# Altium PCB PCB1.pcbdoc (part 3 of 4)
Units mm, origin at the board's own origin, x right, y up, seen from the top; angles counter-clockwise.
Board outline 96.27 x 122.17 mm, 4 copper layers (Top Layer, Inner1, Inner2, Bottom Layer); 129 components, 127 nets, 708 pads, 342 vias.
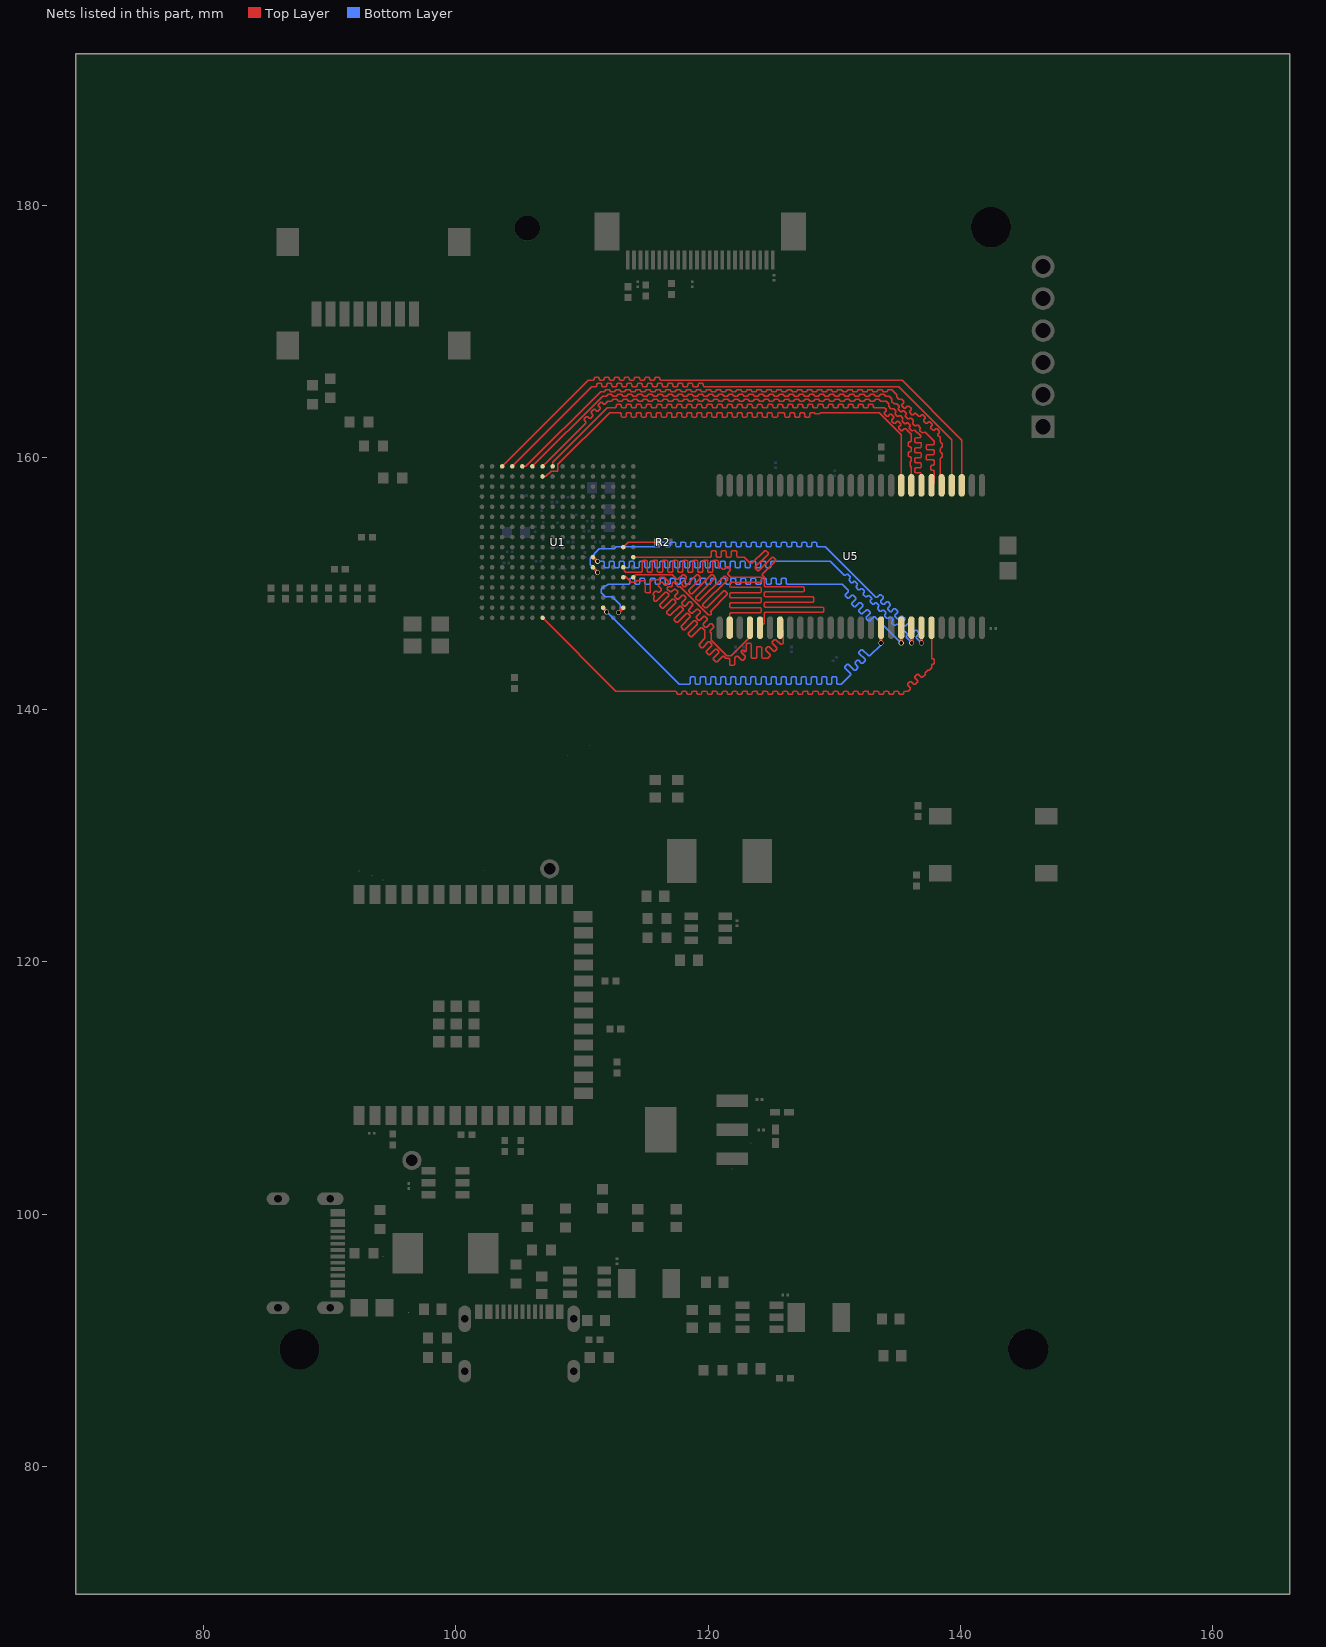
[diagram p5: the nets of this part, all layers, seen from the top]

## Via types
v1: diameter 0.4, hole 0.3, Top Layer to Bottom Layer, 308 vias
v2: diameter 1, hole 0.5, Top Layer to Bottom Layer, 33 vias
v3: diameter 0.5, hole 0.3, Top Layer to Bottom Layer, 1 vias

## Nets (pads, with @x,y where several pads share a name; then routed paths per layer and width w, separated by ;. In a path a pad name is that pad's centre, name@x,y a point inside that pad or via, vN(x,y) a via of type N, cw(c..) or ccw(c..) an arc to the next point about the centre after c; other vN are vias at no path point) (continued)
SD_A5: U1.A3 U5.30 | length 46.8
  Top Layer w0.1: U1.A3@103.677,159.289 110.504,166.116 110.896,166.116 110.967,166.187 110.967,166.27 111.038,166.341 111.296,166.341 111.367,166.27 111.367,166.187 111.438,166.116 111.696,166.116 111.767,166.187 111.767,166.27 111.838,166.341 112.096,166.341 112.167,166.27 112.167,166.187 112.238,166.116 112.496,166.116 112.567,166.187 112.567,166.27 112.638,166.341 112.896,166.341 112.967,166.27 112.967,166.187 113.038,166.116 113.296,166.116 113.367,166.187 113.367,166.27 113.438,166.341 113.696,166.341 113.767,166.27 113.767,166.187 113.838,166.116 114.096,166.116 114.167,166.187 114.167,166.27 114.238,166.341 114.496,166.341 114.567,166.27 114.567,166.187 114.638,166.116 114.896,166.116 114.967,166.187 114.967,166.27 115.038,166.341 115.296,166.341 115.367,166.27 115.367,166.187 115.438,166.116 115.696,166.116 115.767,166.187 115.767,166.27 115.838,166.341 116.096,166.341 116.167,166.27 116.167,166.187 116.238,166.116 135.382,166.116 140.118,161.38 U5.30@140.118,157.788
SD_A6: U1.A4 U5.31 | length 46.7
  Top Layer w0.1: U1.A4@104.477,159.289 110.796,165.608 111.096,165.608 111.167,165.679 111.167,165.791 111.237,165.862 111.496,165.862 111.567,165.791 111.567,165.679 111.637,165.608 111.896,165.608 111.967,165.679 111.967,165.791 112.037,165.862 112.296,165.862 112.367,165.791 112.367,165.679 112.437,165.608 112.696,165.608 112.767,165.679 112.767,165.791 112.837,165.862 113.096,165.862 113.167,165.791 113.167,165.679 113.237,165.608 113.496,165.608 113.567,165.679 113.567,165.791 113.637,165.862 113.896,165.862 113.967,165.791 113.967,165.679 114.037,165.608 114.296,165.608 114.367,165.679 114.367,165.791 114.437,165.862 114.696,165.862 114.767,165.791 114.767,165.679 114.837,165.608 115.096,165.608 115.167,165.679 115.167,165.791 115.237,165.862 115.496,165.862 115.567,165.791 115.567,165.679 115.637,165.608 115.896,165.608 115.967,165.679 115.967,165.791 116.037,165.862 116.296,165.862 116.367,165.791 116.367,165.679 116.437,165.608 116.732,165.608 116.803,165.679 116.803,165.809 116.874,165.879 117.132,165.879 117.203,165.809 117.203,165.679 117.274,165.608 117.532,165.608 117.603,165.679 117.603,165.809 117.674,165.879 117.932,165.879 118.003,165.809 118.003,165.679 118.074,165.608 118.332,165.608 118.403,165.679 118.403,165.809 118.474,165.879 118.732,165.879 118.803,165.809 118.803,165.679 118.874,165.608 119.132,165.608 119.203,165.679 119.203,165.809 119.274,165.879 119.532,165.879 119.603,165.809 119.603,165.679 119.674,165.608 135.128,165.608 139.318,161.418 U5.31@139.318,157.788
SD_A7: U1.A5 U5.32 | length 46.8
  Top Layer w0.1: U1.A5@105.277,159.289 105.537,159.289 111.475,165.227 111.775,165.227 111.902,165.354 112.175,165.354 112.302,165.227 112.575,165.227 112.702,165.354 112.975,165.354 113.102,165.227 113.375,165.227 113.502,165.354 113.775,165.354 113.902,165.227 114.175,165.227 114.302,165.354 114.575,165.354 114.702,165.227 114.975,165.227 115.102,165.354 115.375,165.354 115.502,165.227 115.775,165.227 115.902,165.354 116.175,165.354 116.302,165.227 116.575,165.227 116.702,165.354 116.975,165.354 117.102,165.227 117.375,165.227 117.502,165.354 117.775,165.354 117.902,165.227 118.175,165.227 118.302,165.354 118.575,165.354 118.702,165.227 118.975,165.227 119.102,165.354 119.375,165.354 119.502,165.227 119.775,165.227 119.902,165.354 120.175,165.354 120.302,165.227 120.575,165.227 120.702,165.354 120.975,165.354 121.102,165.227 121.375,165.227 121.502,165.354 121.775,165.354 121.902,165.227 122.175,165.227 122.302,165.354 122.575,165.354 122.702,165.227 122.975,165.227 123.102,165.354 123.375,165.354 123.502,165.227 123.775,165.227 123.902,165.354 124.175,165.354 124.302,165.227 124.575,165.227 124.702,165.354 124.975,165.354 125.102,165.227 125.375,165.227 125.502,165.354 125.775,165.354 125.902,165.227 126.175,165.227 126.302,165.354 126.575,165.354 126.702,165.227 126.975,165.227 127.102,165.354 127.375,165.354 127.502,165.227 127.775,165.227 127.902,165.354 128.175,165.354 128.302,165.227 128.575,165.227 128.702,165.354 128.975,165.354 129.102,165.227 129.375,165.227 129.502,165.354 129.775,165.354 129.902,165.227 130.175,165.227 130.302,165.354 130.575,165.354 130.702,165.227 130.975,165.227 131.102,165.354 131.375,165.354 131.502,165.227 131.775,165.227 131.902,165.354 132.175,165.354 132.302,165.227 132.575,165.227 132.702,165.354 132.975,165.354 133.102,165.227 133.375,165.227 133.502,165.354 133.775,165.354 133.902,165.227 134.175,165.227 134.302,165.354 134.575,165.354 134.947,164.982 134.947,164.803 135.13,164.62 135.23,164.62 135.242,164.632 135.342,164.632 135.525,164.449 135.525,164.349 135.371,164.195 135.371,164.095 135.553,163.912 135.653,163.912 135.808,164.066 135.908,164.066 136.091,163.883 136.091,163.783 135.985,163.678 135.985,163.578 136.168,163.395 136.268,163.395 136.373,163.501 136.473,163.501 136.707,163.267 136.807,163.267 136.926,163.386 137.026,163.386 137.208,163.203 137.208,163.103 137.09,162.984 137.09,162.884 137.272,162.702 137.372,162.702 137.491,162.82 137.591,162.82 137.774,162.638 137.774,162.538 137.655,162.419 137.655,162.319 137.838,162.136 137.938,162.136 138.057,162.255 138.157,162.255 138.34,162.072 138.34,161.972 138.221,161.853 138.221,161.753 138.391,161.583 138.391,161.243 138.462,161.172 138.486,161.172 138.557,161.101 138.557,160.843 138.486,160.772 138.462,160.772 138.391,160.701 138.391,160.443 138.462,160.372 138.486,160.372 138.557,160.301 138.557,160.043 138.486,159.972 138.462,159.972 138.391,159.901 138.391,157.915 U5.32@138.518,157.788
SD_A8: U1.A6 U5.33 | length 46.8
  Top Layer w0.1: U1.A6@106.077,159.289 111.634,164.846 111.934,164.846 112.005,164.917 112.005,164.927 112.075,164.998 112.334,164.998 112.405,164.927 112.405,164.917 112.475,164.846 112.734,164.846 112.805,164.917 112.805,164.927 112.875,164.998 113.134,164.998 113.205,164.927 113.205,164.917 113.275,164.846 113.534,164.846 113.605,164.917 113.605,164.927 113.675,164.998 113.934,164.998 114.005,164.927 114.005,164.917 114.075,164.846 114.334,164.846 114.405,164.917 114.405,164.927 114.475,164.998 114.734,164.998 114.805,164.927 114.805,164.917 114.875,164.846 115.134,164.846 115.205,164.917 115.205,164.927 115.275,164.998 115.534,164.998 115.605,164.927 115.605,164.917 115.675,164.846 115.934,164.846 116.005,164.917 116.005,164.927 116.075,164.998 116.334,164.998 116.405,164.927 116.405,164.917 116.475,164.846 116.734,164.846 116.805,164.917 116.805,164.927 116.875,164.998 117.134,164.998 117.205,164.927 117.205,164.917 117.275,164.846 117.534,164.846 117.605,164.917 117.605,164.927 117.675,164.998 117.934,164.998 118.005,164.927 118.005,164.917 118.075,164.846 118.334,164.846 118.405,164.917 118.405,164.927 118.475,164.998 118.734,164.998 118.805,164.927 118.805,164.917 118.875,164.846 119.134,164.846 119.205,164.917 119.205,164.927 119.275,164.998 119.534,164.998 119.605,164.927 119.605,164.917 119.675,164.846 119.934,164.846 120.005,164.917 120.005,164.927 120.075,164.998 120.334,164.998 120.405,164.927 120.405,164.917 120.475,164.846 120.734,164.846 120.805,164.917 120.805,164.927 120.875,164.998 121.134,164.998 121.205,164.927 121.205,164.917 121.275,164.846 121.534,164.846 121.605,164.917 121.605,164.927 121.675,164.998 121.934,164.998 122.005,164.927 122.005,164.917 122.075,164.846 122.334,164.846 122.405,164.917 122.405,164.927 122.475,164.998 122.734,164.998 122.805,164.927 122.805,164.917 122.875,164.846 123.134,164.846 123.205,164.917 123.205,164.927 123.275,164.998 123.534,164.998 123.605,164.927 123.605,164.917 123.675,164.846 123.934,164.846 124.005,164.917 124.005,164.927 124.075,164.998 124.334,164.998 124.405,164.927 124.405,164.917 124.475,164.846 124.734,164.846 124.805,164.917 124.805,164.927 124.875,164.998 125.134,164.998 125.205,164.927 125.205,164.917 125.275,164.846 125.534,164.846 125.605,164.917 125.605,164.927 125.675,164.998 125.934,164.998 126.005,164.927 126.005,164.917 126.075,164.846 126.334,164.846 126.405,164.917 126.405,164.927 126.475,164.998 126.734,164.998 126.805,164.927 126.805,164.917 126.875,164.846 127.134,164.846 127.205,164.917 127.205,164.927 127.275,164.998 127.534,164.998 127.605,164.927 127.605,164.917 127.675,164.846 127.934,164.846 128.005,164.917 128.005,164.927 128.075,164.998 128.334,164.998 128.405,164.927 128.405,164.917 128.475,164.846 128.734,164.846 128.805,164.917 128.805,164.927 128.875,164.998 129.134,164.998 129.205,164.927 129.205,164.917 129.275,164.846 129.534,164.846 129.605,164.917 129.605,164.927 129.675,164.998 129.934,164.998 130.005,164.927 130.005,164.917 130.075,164.846 130.334,164.846 130.405,164.917 130.405,164.927 130.475,164.998 130.734,164.998 130.805,164.927 130.805,164.917 130.875,164.846 131.134,164.846 131.205,164.917 131.205,164.927 131.275,164.998 131.534,164.998 131.605,164.927 131.605,164.917 131.675,164.846 131.934,164.846 132.005,164.917 132.005,164.927 132.075,164.998 132.334,164.998 132.405,164.927 132.405,164.917 132.475,164.846 132.734,164.846 132.805,164.917 132.805,164.927 132.875,164.998 133.134,164.998 133.205,164.927 133.205,164.917 133.275,164.846 133.534,164.846 133.605,164.917 133.605,164.927 133.675,164.998 133.934,164.998 134.005,164.927 134.005,164.917 134.075,164.846 134.366,164.846 134.578,164.634 134.578,164.534 134.566,164.522 134.566,164.422 134.749,164.239 134.849,164.239 134.861,164.251 134.961,164.251 135.144,164.068 135.144,163.968 135.088,163.913 135.088,163.813 135.271,163.63 135.371,163.63 135.427,163.685 135.527,163.685 135.71,163.502 135.71,163.402 135.654,163.347 135.654,163.247 135.837,163.064 135.937,163.064 135.992,163.12 136.092,163.12 136.275,162.937 136.275,162.837 136.22,162.781 136.22,162.681 136.403,162.499 136.503,162.499 136.558,162.554 136.658,162.554 136.841,162.371 136.841,162.271 136.794,162.225 136.794,162.125 136.977,161.942 137.077,161.942 137.124,161.988 137.224,161.988 137.922,161.29 137.922,161.069 137.851,160.998 137.358,160.998 137.287,160.927 137.287,160.669 137.358,160.598 137.851,160.598 137.922,160.527 137.922,160.269 137.851,160.198 137.358,160.198 137.287,160.127 137.287,159.869 137.358,159.798 137.851,159.798 137.922,159.727 137.922,159.444 137.851,159.373 137.739,159.373 137.668,159.302 137.668,159.044 137.739,158.973 137.851,158.973 137.922,158.902 137.922,157.992 U5.33@137.718,157.788
SD_A9: U1.A7 U5.34 | length 46.8
  Top Layer w0.1: U1.A7@106.877,159.289 110.308,162.72 110.308,162.82 110.17,162.958 110.17,163.058 110.353,163.24 110.453,163.24 110.591,163.103 110.691,163.103 110.874,163.285 110.874,163.385 110.736,163.523 110.736,163.623 110.918,163.806 111.018,163.806 111.156,163.668 111.256,163.668 111.439,163.851 111.439,163.951 111.301,164.089 111.301,164.189 111.484,164.372 111.584,164.372 111.722,164.234 111.822,164.234 112.053,164.465 112.353,164.465 112.424,164.536 112.424,164.546 112.495,164.617 112.753,164.617 112.824,164.546 112.824,164.536 112.895,164.465 113.153,164.465 113.224,164.536 113.224,164.546 113.295,164.617 113.553,164.617 113.624,164.546 113.624,164.536 113.695,164.465 113.953,164.465 114.024,164.536 114.024,164.546 114.095,164.617 114.353,164.617 114.424,164.546 114.424,164.536 114.495,164.465 114.753,164.465 114.824,164.536 114.824,164.546 114.895,164.617 115.153,164.617 115.224,164.546 115.224,164.536 115.295,164.465 115.553,164.465 115.624,164.536 115.624,164.546 115.695,164.617 115.953,164.617 116.024,164.546 116.024,164.536 116.095,164.465 116.353,164.465 116.424,164.536 116.424,164.546 116.495,164.617 116.753,164.617 116.824,164.546 116.824,164.536 116.895,164.465 117.153,164.465 117.224,164.536 117.224,164.546 117.295,164.617 117.553,164.617 117.624,164.546 117.624,164.536 117.695,164.465 117.953,164.465 118.024,164.536 118.024,164.546 118.095,164.617 118.353,164.617 118.424,164.546 118.424,164.536 118.495,164.465 118.753,164.465 118.824,164.536 118.824,164.546 118.895,164.617 119.153,164.617 119.224,164.546 119.224,164.536 119.295,164.465 119.553,164.465 119.624,164.536 119.624,164.546 119.695,164.617 119.953,164.617 120.024,164.546 120.024,164.536 120.095,164.465 120.353,164.465 120.424,164.536 120.424,164.546 120.495,164.617 120.753,164.617 120.824,164.546 120.824,164.536 120.895,164.465 121.153,164.465 121.224,164.536 121.224,164.546 121.295,164.617 121.553,164.617 121.624,164.546 121.624,164.536 121.695,164.465 121.953,164.465 122.024,164.536 122.024,164.546 122.095,164.617 122.353,164.617 122.424,164.546 122.424,164.536 122.495,164.465 122.753,164.465 122.824,164.536 122.824,164.546 122.895,164.617 123.153,164.617 123.224,164.546 123.224,164.536 123.295,164.465 123.553,164.465 123.624,164.536 123.624,164.546 123.695,164.617 123.953,164.617 124.024,164.546 124.024,164.536 124.095,164.465 124.353,164.465 124.424,164.536 124.424,164.546 124.495,164.617 124.753,164.617 124.824,164.546 124.824,164.536 124.895,164.465 125.153,164.465 125.224,164.536 125.224,164.546 125.295,164.617 125.553,164.617 125.624,164.546 125.624,164.536 125.695,164.465 125.953,164.465 126.024,164.536 126.024,164.546 126.095,164.617 126.353,164.617 126.424,164.546 126.424,164.536 126.495,164.465 126.753,164.465 126.824,164.536 126.824,164.546 126.895,164.617 127.153,164.617 127.224,164.546 127.224,164.536 127.295,164.465 127.553,164.465 127.624,164.536 127.624,164.546 127.695,164.617 127.953,164.617 128.024,164.546 128.024,164.536 128.095,164.465 128.353,164.465 128.424,164.536 128.424,164.546 128.495,164.617 128.753,164.617 128.824,164.546 128.824,164.536 128.895,164.465 129.153,164.465 129.224,164.536 129.224,164.546 129.295,164.617 129.553,164.617 129.624,164.546 129.624,164.536 129.695,164.465 129.953,164.465 130.024,164.536 130.024,164.546 130.095,164.617 130.353,164.617 130.424,164.546 130.424,164.536 130.495,164.465 130.753,164.465 130.824,164.536 130.824,164.546 130.895,164.617 131.153,164.617 131.224,164.546 131.224,164.536 131.295,164.465 131.553,164.465 131.624,164.536 131.624,164.546 131.695,164.617 131.953,164.617 132.024,164.546 132.024,164.536 132.095,164.465 132.353,164.465 132.424,164.536 132.424,164.546 132.495,164.617 132.753,164.617 132.824,164.546 132.824,164.536 132.895,164.465 133.153,164.465 133.224,164.536 133.224,164.546 133.295,164.617 133.553,164.617 133.624,164.546 133.624,164.536 133.695,164.465 134.112,164.465 134.324,164.253 134.324,164.153 134.312,164.141 134.312,164.041 134.495,163.858 134.595,163.858 134.607,163.87 134.707,163.87 134.89,163.687 134.89,163.587 134.834,163.532 134.834,163.432 135.017,163.249 135.117,163.249 135.173,163.304 135.273,163.304 135.456,163.121 135.456,163.021 135.4,162.966 135.4,162.866 135.583,162.683 135.683,162.683 135.738,162.739 135.838,162.739 136.021,162.556 136.021,162.456 135.966,162.4 135.966,162.3 136.149,162.118 136.249,162.118 136.304,162.173 136.404,162.173 136.847,161.73 136.847,161.651 136.777,161.58 136.469,161.58 136.398,161.51 136.398,161.251 136.469,161.18 136.847,161.18 136.918,161.11 136.918,160.851 136.847,160.78 136.469,160.78 136.398,160.71 136.398,160.451 136.469,160.38 136.847,160.38 136.918,160.31 136.918,160.051 136.847,159.98 136.469,159.98 136.398,159.91 136.398,159.651 136.469,159.58 136.847,159.58 136.918,159.51 136.918,159.251 136.847,159.18 136.469,159.18 136.398,159.11 136.398,158.851 136.469,158.78 136.847,158.78 136.918,158.71 U5.34@136.918,157.788
SD_A10: U1.T7 U5.22 | length 46.9
  Top Layer w0.1: U1.T7@106.877,147.289 112.688,141.478 117.449,141.478 117.519,141.407 117.519,141.295 117.59,141.224 117.849,141.224 117.919,141.295 117.919,141.407 117.99,141.478 118.249,141.478 118.319,141.407 118.319,141.295 118.39,141.224 118.649,141.224 118.719,141.295 118.719,141.407 118.79,141.478 119.049,141.478 119.119,141.407 119.119,141.295 119.19,141.224 119.449,141.224 119.519,141.295 119.519,141.407 119.59,141.478 119.849,141.478 119.919,141.407 119.919,141.295 119.99,141.224 120.249,141.224 120.319,141.295 120.319,141.407 120.39,141.478 120.649,141.478 120.719,141.407 120.719,141.295 120.79,141.224 121.049,141.224 121.119,141.295 121.119,141.407 121.19,141.478 121.449,141.478 121.519,141.407 121.519,141.295 121.59,141.224 121.849,141.224 121.919,141.295 121.919,141.407 121.99,141.478 122.249,141.478 122.319,141.407 122.319,141.295 122.39,141.224 122.649,141.224 122.719,141.295 122.719,141.407 122.79,141.478 123.049,141.478 123.119,141.407 123.119,141.295 123.19,141.224 123.449,141.224 123.519,141.295 123.519,141.407 123.59,141.478 123.849,141.478 123.919,141.407 123.919,141.295 123.99,141.224 124.249,141.224 124.319,141.295 124.319,141.407 124.39,141.478 124.649,141.478 124.719,141.407 124.719,141.295 124.79,141.224 125.049,141.224 125.119,141.295 125.119,141.407 125.19,141.478 125.449,141.478 125.519,141.407 125.519,141.295 125.59,141.224 125.849,141.224 125.919,141.295 125.919,141.407 125.99,141.478 126.249,141.478 126.319,141.407 126.319,141.295 126.39,141.224 126.649,141.224 126.719,141.295 126.719,141.407 126.79,141.478 127.049,141.478 127.119,141.407 127.119,141.295 127.19,141.224 127.449,141.224 127.519,141.295 127.519,141.407 127.59,141.478 127.849,141.478 127.919,141.407 127.919,141.295 127.99,141.224 128.249,141.224 128.319,141.295 128.319,141.407 128.39,141.478 128.649,141.478 128.719,141.407 128.719,141.295 128.79,141.224 129.049,141.224 129.119,141.295 129.119,141.407 129.19,141.478 129.449,141.478 129.519,141.407 129.519,141.295 129.59,141.224 129.849,141.224 129.919,141.295 129.919,141.407 129.99,141.478 130.249,141.478 130.319,141.407 130.319,141.295 130.39,141.224 130.649,141.224 130.719,141.295 130.719,141.407 130.79,141.478 131.049,141.478 131.119,141.407 131.119,141.295 131.19,141.224 131.449,141.224 131.519,141.295 131.519,141.407 131.59,141.478 131.849,141.478 131.919,141.407 131.919,141.295 131.99,141.224 132.249,141.224 132.319,141.295 132.319,141.407 132.39,141.478 132.649,141.478 132.719,141.407 132.719,141.295 132.79,141.224 133.049,141.224 133.119,141.295 133.119,141.407 133.19,141.478 133.449,141.478 133.519,141.407 133.519,141.295 133.59,141.224 133.849,141.224 133.919,141.295 133.919,141.407 133.99,141.478 134.249,141.478 134.319,141.407 134.319,141.295 134.39,141.224 134.649,141.224 134.719,141.295 134.719,141.407 134.79,141.478 135.049,141.478 135.119,141.407 135.119,141.295 135.19,141.224 135.449,141.224 135.519,141.295 135.519,141.407 135.59,141.478 135.89,141.478 136.044,141.632 136.044,141.732 135.826,141.949 135.826,142.049 136.009,142.232 136.109,142.232 136.327,142.015 136.427,142.015 136.61,142.198 136.61,142.298 136.392,142.515 136.392,142.615 136.575,142.798 136.675,142.798 136.893,142.581 136.993,142.581 137.202,142.79 137.202,142.931 137.414,143.143 137.555,143.143 137.718,143.306 137.718,143.549 137.789,143.62 137.851,143.62 137.922,143.69 137.922,143.949 137.851,144.02 137.789,144.02 137.718,144.09 U5.22@137.718,146.504
SD_A11: U1.A8 U5.35 | length 46.7
  Top Layer w0.1: U1.A8@107.677,159.289 107.677,159.62 112.014,163.957 112.645,163.957 112.716,164.028 112.716,164.14 112.786,164.211 113.045,164.211 113.116,164.14 113.116,164.028 113.186,163.957 113.445,163.957 113.516,164.028 113.516,164.14 113.586,164.211 113.845,164.211 113.916,164.14 113.916,164.028 113.986,163.957 114.245,163.957 114.316,164.028 114.316,164.14 114.386,164.211 114.645,164.211 114.716,164.14 114.716,164.028 114.786,163.957 115.045,163.957 115.116,164.028 115.116,164.14 115.186,164.211 115.445,164.211 115.516,164.14 115.516,164.028 115.586,163.957 115.845,163.957 115.916,164.028 115.916,164.14 115.986,164.211 116.245,164.211 116.316,164.14 116.316,164.028 116.386,163.957 116.645,163.957 116.716,164.028 116.716,164.14 116.786,164.211 117.045,164.211 117.116,164.14 117.116,164.028 117.186,163.957 117.445,163.957 117.516,164.028 117.516,164.14 117.586,164.211 117.845,164.211 117.916,164.14 117.916,164.028 117.986,163.957 118.245,163.957 118.316,164.028 118.316,164.14 118.386,164.211 118.645,164.211 118.716,164.14 118.716,164.028 118.786,163.957 119.045,163.957 119.116,164.028 119.116,164.14 119.186,164.211 119.445,164.211 119.516,164.14 119.516,164.028 119.586,163.957 119.845,163.957 119.916,164.028 119.916,164.14 119.986,164.211 120.245,164.211 120.316,164.14 120.316,164.028 120.386,163.957 120.645,163.957 120.716,164.028 120.716,164.14 120.786,164.211 121.045,164.211 121.116,164.14 121.116,164.028 121.186,163.957 121.445,163.957 121.516,164.028 121.516,164.14 121.586,164.211 121.845,164.211 121.916,164.14 121.916,164.028 121.986,163.957 122.245,163.957 122.316,164.028 122.316,164.14 122.386,164.211 122.645,164.211 122.716,164.14 122.716,164.028 122.786,163.957 123.045,163.957 123.116,164.028 123.116,164.14 123.186,164.211 123.445,164.211 123.516,164.14 123.516,164.028 123.586,163.957 123.845,163.957 123.916,164.028 123.916,164.14 123.986,164.211 124.245,164.211 124.316,164.14 124.316,164.028 124.386,163.957 124.645,163.957 124.716,164.028 124.716,164.14 124.786,164.211 125.045,164.211 125.116,164.14 125.116,164.028 125.186,163.957 125.445,163.957 125.516,164.028 125.516,164.14 125.586,164.211 125.845,164.211 125.916,164.14 125.916,164.028 125.986,163.957 126.245,163.957 126.316,164.028 126.316,164.14 126.386,164.211 126.645,164.211 126.716,164.14 126.716,164.028 126.786,163.957 127.045,163.957 127.116,164.028 127.116,164.14 127.186,164.211 127.445,164.211 127.516,164.14 127.516,164.028 127.586,163.957 127.845,163.957 127.916,164.028 127.916,164.14 127.986,164.211 128.245,164.211 128.316,164.14 128.316,164.028 128.386,163.957 128.645,163.957 128.716,164.028 128.716,164.14 128.786,164.211 129.045,164.211 129.116,164.14 129.116,164.028 129.186,163.957 129.445,163.957 129.516,164.028 129.516,164.14 129.586,164.211 129.845,164.211 129.916,164.14 129.916,164.028 129.986,163.957 130.245,163.957 130.316,164.028 130.316,164.14 130.386,164.211 130.645,164.211 130.716,164.14 130.716,164.028 130.786,163.957 131.045,163.957 131.116,164.028 131.116,164.14 131.186,164.211 131.445,164.211 131.516,164.14 131.516,164.028 131.586,163.957 131.845,163.957 131.916,164.028 131.916,164.14 131.986,164.211 132.245,164.211 132.316,164.14 132.316,164.028 132.386,163.957 132.645,163.957 132.716,164.028 132.716,164.14 132.786,164.211 133.045,164.211 133.116,164.14 133.116,164.028 133.186,163.957 133.985,163.957 134.14,163.802 134.14,163.702 133.986,163.548 133.986,163.448 134.169,163.265 134.269,163.265 134.423,163.419 134.523,163.419 134.706,163.236 134.706,163.136 134.552,162.982 134.552,162.882 134.735,162.699 134.835,162.699 134.989,162.853 135.089,162.853 135.272,162.67 135.272,162.57 135.118,162.416 135.118,162.316 135.301,162.133 135.401,162.133 135.555,162.287 135.655,162.287 136.118,161.824 136.118,161.306 136.047,161.235 135.961,161.235 135.89,161.164 135.89,160.906 135.961,160.835 136.047,160.835 136.118,160.764 136.118,160.506 136.047,160.435 135.961,160.435 135.89,160.364 135.89,160.106 135.961,160.035 136.047,160.035 136.118,159.964 136.118,159.742 136.017,159.641 136.017,159.342 136.118,159.241 U5.35@136.118,157.788
SD_A12: U1.B7 U5.36 | length 46.8
  Top Layer w0.1: U1.B7@106.877,158.489 107.137,158.489 107.555,158.907 108.07,158.907 108.095,158.932 108.095,159.447 112.197,163.549 113.037,163.549 113.108,163.478 113.108,163.239 113.178,163.168 113.437,163.168 113.508,163.239 113.508,163.478 113.578,163.549 113.837,163.549 113.908,163.478 113.908,163.239 113.978,163.168 114.237,163.168 114.308,163.239 114.308,163.478 114.378,163.549 114.637,163.549 114.708,163.478 114.708,163.239 114.778,163.168 115.037,163.168 115.108,163.239 115.108,163.478 115.178,163.549 115.437,163.549 115.508,163.478 115.508,163.239 115.578,163.168 115.837,163.168 115.908,163.239 115.908,163.478 115.978,163.549 116.237,163.549 116.308,163.478 116.308,163.239 116.378,163.168 116.637,163.168 116.708,163.239 116.708,163.478 116.778,163.549 117.037,163.549 117.108,163.478 117.108,163.239 117.178,163.168 117.437,163.168 117.508,163.239 117.508,163.478 117.578,163.549 117.837,163.549 117.908,163.478 117.908,163.239 117.978,163.168 118.237,163.168 118.308,163.239 118.308,163.478 118.378,163.549 118.637,163.549 118.708,163.478 118.708,163.239 118.778,163.168 119.037,163.168 119.108,163.239 119.108,163.478 119.178,163.549 119.437,163.549 119.508,163.478 119.508,163.239 119.578,163.168 119.837,163.168 119.908,163.239 119.908,163.478 119.978,163.549 120.237,163.549 120.308,163.478 120.308,163.239 120.378,163.168 120.637,163.168 120.708,163.239 120.708,163.478 120.778,163.549 121.037,163.549 121.108,163.478 121.108,163.239 121.178,163.168 121.437,163.168 121.508,163.239 121.508,163.478 121.578,163.549 121.837,163.549 121.908,163.478 121.908,163.239 121.978,163.168 122.237,163.168 122.308,163.239 122.308,163.478 122.378,163.549 122.637,163.549 122.708,163.478 122.708,163.239 122.778,163.168 123.037,163.168 123.108,163.239 123.108,163.478 123.178,163.549 123.437,163.549 123.508,163.478 123.508,163.239 123.578,163.168 123.837,163.168 123.908,163.239 123.908,163.478 123.978,163.549 124.237,163.549 124.308,163.478 124.308,163.239 124.378,163.168 124.637,163.168 124.708,163.239 124.708,163.478 124.778,163.549 125.037,163.549 125.108,163.478 125.108,163.239 125.178,163.168 125.437,163.168 125.508,163.239 125.508,163.478 125.578,163.549 125.993,163.549 126.063,163.478 126.063,163.266 126.134,163.195 126.393,163.195 126.463,163.266 126.463,163.478 126.534,163.549 126.793,163.549 126.863,163.478 126.863,163.266 126.934,163.195 127.193,163.195 127.263,163.266 127.263,163.478 127.334,163.549 127.593,163.549 127.663,163.478 127.663,163.266 127.734,163.195 127.993,163.195 128.063,163.266 128.063,163.478 128.134,163.549 128.416,163.549 128.516,163.449 128.816,163.449 128.916,163.549 133.577,163.549 135.318,161.808 U5.36@135.318,157.788
SD_BA0: U1.K12 U5.20 | length 46.8
  Top Layer w0.254: U1.K12@110.877,152.089 111.203,151.763 v1(111.25,151.763) ; U5.20@136.118,146.504 136.144,146.478 v1(136.144,145.288)
  Bottom Layer w0.1: v1(111.25,151.763) 111.691,151.763 111.762,151.693 111.762,151.337 111.833,151.266 112.091,151.266 112.162,151.337 112.162,151.693 112.233,151.763 112.491,151.763 112.562,151.693 112.562,151.337 112.633,151.266 112.891,151.266 112.962,151.337 112.962,151.693 113.033,151.763 113.291,151.763 113.362,151.693 113.362,151.337 113.433,151.266 113.691,151.266 113.762,151.337 113.762,151.693 113.833,151.763 114.091,151.763 114.162,151.693 114.162,151.337 114.233,151.266 114.491,151.266 114.562,151.337 114.562,151.693 114.633,151.763 114.891,151.763 114.962,151.693 114.962,151.337 115.033,151.266 115.291,151.266 115.362,151.337 115.362,151.693 115.433,151.763 115.691,151.763 115.762,151.693 115.762,151.337 115.833,151.266 116.091,151.266 116.162,151.337 116.162,151.693 116.233,151.763 116.491,151.763 116.562,151.693 116.562,151.337 116.633,151.266 116.891,151.266 116.962,151.337 116.962,151.693 117.033,151.763 117.291,151.763 117.362,151.693 117.362,151.337 117.433,151.266 117.691,151.266 117.762,151.337 117.762,151.693 117.833,151.763 118.091,151.763 118.162,151.693 118.162,151.337 118.233,151.266 118.491,151.266 118.562,151.337 118.562,151.693 118.633,151.763 118.891,151.763 118.962,151.693 118.962,151.337 119.033,151.266 119.291,151.266 119.362,151.337 119.362,151.693 119.433,151.763 119.691,151.763 119.762,151.693 119.762,151.337 119.833,151.266 120.091,151.266 120.162,151.337 120.162,151.693 120.233,151.763 120.491,151.763 120.562,151.693 120.562,151.337 120.633,151.266 120.891,151.266 120.962,151.337 120.962,151.693 121.033,151.763 121.291,151.763 121.362,151.693 121.362,151.337 121.433,151.266 121.691,151.266 121.762,151.337 121.762,151.693 121.833,151.763 122.091,151.763 122.162,151.693 122.162,151.337 122.233,151.266 122.491,151.266 122.562,151.337 122.562,151.693 122.633,151.763 122.891,151.763 122.962,151.693 122.962,151.337 123.033,151.266 123.291,151.266 123.362,151.337 123.362,151.693 123.433,151.763 123.691,151.763 123.762,151.693 123.762,151.337 123.833,151.266 124.091,151.266 124.162,151.337 124.162,151.693 124.233,151.763 124.491,151.763 124.562,151.693 124.562,151.337 124.633,151.266 124.891,151.266 124.962,151.337 124.962,151.693 125.033,151.763 129.669,151.763 130.793,150.639 130.893,150.639 130.983,150.73 131.083,150.73 131.266,150.547 131.266,150.447 131.176,150.356 131.176,150.256 131.358,150.074 131.458,150.074 131.549,150.164 131.649,150.164 131.832,149.981 131.832,149.881 131.741,149.791 131.741,149.691 131.924,149.508 132.024,149.508 132.115,149.598 132.215,149.598 132.397,149.416 132.397,149.316 132.307,149.225 132.307,149.125 132.49,148.942 132.59,148.942 132.68,149.033 132.78,149.033 132.963,148.85 132.963,148.75 132.873,148.659 132.873,148.559 133.055,148.377 133.155,148.377 133.246,148.467 133.346,148.467 133.529,148.284 133.529,148.184 133.438,148.094 133.438,147.994 133.621,147.811 133.721,147.811 133.812,147.901 133.912,147.901 134.095,147.718 134.095,147.618 134.004,147.528 134.004,147.428 134.187,147.245 134.287,147.245 134.377,147.336 134.477,147.336 134.66,147.153 134.66,147.053 134.57,146.962 134.57,146.862 134.753,146.679 134.853,146.679 134.943,146.77 135.043,146.77 135.226,146.587 135.226,146.487 135.135,146.397 135.135,146.297 135.318,146.114 135.418,146.114 135.509,146.204 135.609,146.204 135.792,146.021 135.792,145.921 135.701,145.831 135.701,145.731 v1(136.144,145.288)
SD_BA1: U1.L12 U5.21 | length 46.8
  Top Layer w0.254: U1.L12@110.877,151.289 111.252,150.914 v1(111.252,150.876) ; v1(136.918,145.288) U5.21@136.918,146.504
  Bottom Layer w0.1: v1(111.252,150.876) 110.648,151.48 110.648,152.013 111.389,152.753 112.581,152.753 112.736,152.908 116.151,152.908 116.222,152.979 116.222,153.218 116.293,153.289 116.551,153.289 116.622,153.218 116.622,152.979 116.693,152.908 116.951,152.908 117.022,152.979 117.022,153.218 117.093,153.289 117.351,153.289 117.422,153.218 117.422,152.979 117.493,152.908 117.751,152.908 117.822,152.979 117.822,153.218 117.893,153.289 118.151,153.289 118.222,153.218 118.222,152.979 118.293,152.908 118.551,152.908 118.622,152.979 118.622,153.218 118.693,153.289 118.951,153.289 119.022,153.218 119.022,152.979 119.093,152.908 119.351,152.908 119.422,152.979 119.422,153.218 119.493,153.289 119.751,153.289 119.822,153.218 119.822,152.979 119.893,152.908 120.151,152.908 120.222,152.979 120.222,153.218 120.293,153.289 120.551,153.289 120.622,153.218 120.622,152.979 120.693,152.908 120.951,152.908 121.022,152.979 121.022,153.218 121.093,153.289 121.351,153.289 121.422,153.218 121.422,152.979 121.493,152.908 121.751,152.908 121.822,152.979 121.822,153.218 121.893,153.289 122.151,153.289 122.222,153.218 122.222,152.979 122.293,152.908 122.551,152.908 122.622,152.979 122.622,153.218 122.693,153.289 122.951,153.289 123.022,153.218 123.022,152.979 123.093,152.908 123.351,152.908 123.422,152.979 123.422,153.218 123.493,153.289 123.751,153.289 123.822,153.218 123.822,152.979 123.893,152.908 124.151,152.908 124.222,152.979 124.222,153.218 124.293,153.289 124.551,153.289 124.622,153.218 124.622,152.979 124.693,152.908 124.951,152.908 125.022,152.979 125.022,153.218 125.093,153.289 125.351,153.289 125.422,153.218 125.422,152.979 125.493,152.908 125.751,152.908 125.822,152.979 125.822,153.218 125.893,153.289 126.151,153.289 126.222,153.218 126.222,152.979 126.293,152.908 126.551,152.908 126.622,152.979 126.622,153.218 126.693,153.289 126.951,153.289 127.022,153.218 127.022,152.979 127.093,152.908 127.351,152.908 127.422,152.979 127.422,153.218 127.493,153.289 127.751,153.289 127.822,153.218 127.822,152.979 127.893,152.908 128.151,152.908 128.222,152.979 128.222,153.218 128.293,153.289 128.551,153.289 128.622,153.218 128.622,152.979 128.693,152.908 129.298,152.908 133.297,148.908 133.397,148.908 133.609,149.12 133.709,149.12 133.892,148.937 133.892,148.837 133.68,148.626 133.68,148.526 133.863,148.343 133.963,148.343 134.175,148.554 134.275,148.554 134.458,148.371 134.458,148.271 134.246,148.06 134.246,147.96 134.429,147.777 134.529,147.777 134.74,147.989 134.84,147.989 135.023,147.806 135.023,147.706 134.812,147.494 134.812,147.394 134.995,147.211 135.095,147.211 135.306,147.423 135.406,147.423 135.589,147.24 135.589,147.14 135.377,146.929 135.377,146.829 135.56,146.646 135.66,146.646 135.872,146.857 135.972,146.857 136.155,146.674 136.155,146.574 135.943,146.363 135.943,146.263 136.126,146.08 136.226,146.08 136.437,146.292 136.537,146.292 136.72,146.109 136.72,146.009 136.509,145.797 136.509,145.697 v1(136.918,145.288)
SD_CAS_N: U1.R13 U5.17 | length 46.8
  Top Layer w0.254: U1.R13@111.677,148.089 111.677,148.041 v1(111.966,147.753) ; v1(133.718,145.288) U5.17@133.718,146.504
  Bottom Layer w0.1: v1(111.966,147.753) 117.709,142.009 118.529,142.009 118.6,142.08 118.6,142.55 118.67,142.621 118.929,142.621 119,142.55 119,142.08 119.07,142.009 119.329,142.009 119.4,142.08 119.4,142.55 119.47,142.621 119.729,142.621 119.8,142.55 119.8,142.08 119.87,142.009 120.129,142.009 120.2,142.08 120.2,142.55 120.27,142.621 120.529,142.621 120.6,142.55 120.6,142.08 120.67,142.009 120.929,142.009 121,142.08 121,142.55 121.07,142.621 121.329,142.621 121.4,142.55 121.4,142.08 121.47,142.009 121.729,142.009 121.8,142.08 121.8,142.55 121.87,142.621 122.129,142.621 122.2,142.55 122.2,142.08 122.27,142.009 122.529,142.009 122.6,142.08 122.6,142.55 122.67,142.621 122.929,142.621 123,142.55 123,142.08 123.07,142.009 123.329,142.009 123.4,142.08 123.4,142.55 123.47,142.621 123.729,142.621 123.8,142.55 123.8,142.08 123.87,142.009 124.129,142.009 124.2,142.08 124.2,142.55 124.27,142.621 124.529,142.621 124.6,142.55 124.6,142.08 124.67,142.009 124.929,142.009 125,142.08 125,142.55 125.07,142.621 125.329,142.621 125.4,142.55 125.4,142.08 125.47,142.009 125.729,142.009 125.8,142.08 125.8,142.55 125.87,142.621 126.129,142.621 126.2,142.55 126.2,142.08 126.27,142.009 126.529,142.009 126.6,142.08 126.6,142.55 126.67,142.621 126.929,142.621 127,142.55 127,142.08 127.07,142.009 127.329,142.009 127.4,142.08 127.4,142.55 127.47,142.621 127.729,142.621 127.8,142.55 127.8,142.08 127.87,142.009 128.129,142.009 128.2,142.08 128.2,142.55 128.27,142.621 128.529,142.621 128.6,142.55 128.6,142.08 128.67,142.009 128.929,142.009 129,142.08 129,142.55 129.07,142.621 129.329,142.621 129.4,142.55 129.4,142.08 129.47,142.009 129.729,142.009 129.8,142.08 129.8,142.55 129.87,142.621 130.129,142.621 130.2,142.55 130.2,142.08 130.27,142.009 130.57,142.009 131.313,142.751 131.313,142.851 130.845,143.319 130.845,143.419 131.028,143.602 131.128,143.602 131.596,143.134 131.696,143.134 131.878,143.317 131.878,143.417 131.653,143.643 131.653,143.743 131.836,143.926 131.936,143.926 132.161,143.7 132.261,143.7 132.444,143.883 132.444,143.983 131.96,144.467 131.96,144.567 132.143,144.749 132.243,144.749 132.727,144.266 132.827,144.266 133.718,145.157 v1(133.718,145.288)
SD_CLK: R2.2 U1.J15 | length 2.9
  Top Layer w0.1: U1.J15@113.277,152.889 113.677,153.289 R2.2@116.026,153.289
SD_CS_N: U1.R15 U5.19 | length 46.8
  Top Layer w0.254: v1(112.903,147.701) 113.277,148.075 U1.R15@113.277,148.089 ; v1(135.318,145.288) U5.19@135.318,146.504
  Bottom Layer w0.1: v1(112.903,147.701) 113.03,147.701 113.03,148.336 112.416,148.95 111.847,148.95 111.535,149.262 111.535,149.55 111.816,149.831 111.943,149.831 112.07,149.958 113.73,149.958 113.8,150.029 113.8,150.358 113.871,150.429 114.13,150.429 114.2,150.358 114.2,150.029 114.271,149.958 114.53,149.958 114.6,150.029 114.6,150.358 114.671,150.429 114.93,150.429 115,150.358 115,150.029 115.071,149.958 115.33,149.958 115.4,150.029 115.4,150.358 115.471,150.429 115.73,150.429 115.8,150.358 115.8,150.029 115.871,149.958 116.13,149.958 116.2,150.029 116.2,150.358 116.271,150.429 116.53,150.429 116.6,150.358 116.6,150.029 116.671,149.958 116.93,149.958 117,150.029 117,150.358 117.071,150.429 117.33,150.429 117.4,150.358 117.4,150.029 117.471,149.958 117.73,149.958 117.8,150.029 117.8,150.358 117.871,150.429 118.13,150.429 118.2,150.358 118.2,150.029 118.271,149.958 118.53,149.958 118.6,150.029 118.6,150.358 118.671,150.429 118.93,150.429 119,150.358 119,150.029 119.071,149.958 119.33,149.958 119.4,150.029 119.4,150.358 119.471,150.429 119.73,150.429 119.8,150.358 119.8,150.029 119.871,149.958 120.13,149.958 120.2,150.029 120.2,150.358 120.271,150.429 120.53,150.429 120.6,150.358 120.6,150.029 120.671,149.958 120.93,149.958 121,150.029 121,150.358 121.071,150.429 121.33,150.429 121.4,150.358 121.4,150.029 121.471,149.958 121.73,149.958 121.8,150.029 121.8,150.358 121.871,150.429 122.13,150.429 122.2,150.358 122.2,150.029 122.271,149.958 122.53,149.958 122.6,150.029 122.6,150.358 122.671,150.429 122.93,150.429 123,150.358 123,150.029 123.071,149.958 123.33,149.958 123.4,150.029 123.4,150.358 123.471,150.429 123.73,150.429 123.8,150.358 123.8,150.029 123.871,149.958 124.13,149.958 124.2,150.029 124.2,150.358 124.271,150.429 124.53,150.429 124.6,150.358 124.6,150.029 124.671,149.958 124.93,149.958 125,150.029 125,150.358 125.071,150.429 125.33,150.429 125.4,150.358 125.4,150.029 125.471,149.958 125.73,149.958 125.8,150.029 125.8,150.358 125.871,150.429 126.13,150.429 126.2,150.358 126.2,150.029 126.271,149.958 130.627,149.958 131.119,149.466 131.119,149.366 130.881,149.127 130.881,149.027 131.064,148.844 131.164,148.844 131.402,149.083 131.502,149.083 131.714,148.871 131.714,148.771 131.395,148.453 131.395,148.353 131.578,148.17 131.678,148.17 131.997,148.489 132.097,148.489 132.28,148.306 132.28,148.206 131.961,147.887 131.961,147.787 132.144,147.604 132.244,147.604 132.563,147.923 132.663,147.923 132.845,147.74 132.845,147.64 132.527,147.321 132.527,147.221 132.71,147.039 132.81,147.039 133.128,147.357 133.228,147.357 135.17,145.415 135.191,145.415 v1(135.318,145.288)
SD_DQ0: U1.L15 U5.2 | length 46.8
  Top Layer w0.1: U1.L15@113.277,151.289 113.374,151.192 113.374,151.007 113.474,150.907 114.719,150.907 114.79,150.978 114.79,151.789 114.86,151.86 115.119,151.86 115.19,151.789 115.19,150.978 115.26,150.907 115.519,150.907 115.59,150.978 115.59,151.789 115.66,151.86 115.919,151.86 115.99,151.789 115.99,150.978 116.06,150.907 116.319,150.907 116.39,150.978 116.39,151.789 116.46,151.86 116.719,151.86 116.79,151.789 116.79,150.978 116.86,150.907 117.119,150.907 117.19,150.978 117.19,151.789 117.26,151.86 117.519,151.86 117.59,151.789 117.59,150.978 117.66,150.907 117.919,150.907 117.99,150.978 117.99,151.789 118.06,151.86 118.319,151.86 118.39,151.789 118.39,150.978 118.46,150.907 118.719,150.907 118.79,150.978 118.79,151.789 118.86,151.86 119.119,151.86 119.19,151.789 119.19,150.978 119.26,150.907 119.519,150.907 119.59,150.978 119.59,151.789 119.66,151.86 119.919,151.86 119.99,151.789 119.99,150.978 120.06,150.907 120.319,150.907 120.39,150.978 120.39,151.789 120.46,151.86 120.719,151.86 120.79,151.789 120.79,151.328 120.86,151.257 121.031,151.257 121.169,151.119 121.269,151.119 121.487,151.336 121.587,151.336 121.77,151.153 121.77,151.053 121.552,150.836 121.552,150.736 121.718,150.57 121.718,150.561 121.789,150.49 124.182,150.49 124.253,150.419 124.253,150.161 124.182,150.09 121.789,150.09 121.718,150.019 121.718,149.761 121.789,149.69 124.16,149.69 124.231,149.619 124.231,149.361 124.16,149.29 121.789,149.29 121.718,149.219 121.718,148.961 121.789,148.89 124.16,148.89 124.231,148.819 124.231,148.561 124.16,148.49 121.789,148.49 121.718,148.419 121.718,148.161 121.789,148.09 124.16,148.09 124.231,148.019 124.231,147.761 124.16,147.69 121.789,147.69 121.718,147.619 U5.2@121.718,146.504
SD_DQ1: U1.M16 U5.4 | length 46.9
  Top Layer w0.1: U1.M16@114.077,150.489 114.286,150.698 117.145,150.698 117.515,150.328 117.615,150.328 117.994,150.707 118.094,150.707 118.277,150.524 118.277,150.424 117.898,150.045 117.898,149.945 118.081,149.762 118.181,149.762 119.116,150.698 119.216,150.698 119.399,150.515 119.399,150.415 118.464,149.479 118.464,149.379 118.647,149.196 118.747,149.196 120.257,150.707 120.357,150.707 120.54,150.524 120.54,150.424 119.029,148.914 119.029,148.814 119.212,148.631 119.312,148.631 121.268,150.587 121.368,150.587 121.551,150.404 121.551,150.304 119.595,148.348 119.595,148.248 119.778,148.065 119.878,148.065 121.235,149.422 121.335,149.422 121.518,149.24 121.518,149.14 120.161,147.782 120.197,147.782 120.269,147.71 120.269,147.586 120.198,147.515 120.035,147.515 117.789,149.761 117.632,149.761 117.562,149.832 117.562,150.028 117.491,150.099 117.232,150.099 117.162,150.028 117.162,149.832 117.091,149.761 116.862,149.761 116.781,149.68 116.781,149.538 116.984,149.335 117.084,149.335 117.311,149.561 117.411,149.561 117.594,149.378 117.594,149.278 117.367,149.052 117.367,148.952 117.55,148.769 117.65,148.769 117.966,149.085 118.066,149.085 118.249,148.902 118.249,148.802 117.933,148.486 117.933,148.386 118.098,148.221 118.198,148.221 118.521,148.544 118.621,148.544 118.804,148.361 118.804,148.261 118.481,147.938 118.481,147.838 118.664,147.655 118.764,147.655 119.087,147.978 119.187,147.978 119.37,147.796 119.37,147.696 119.047,147.372 119.047,147.272 119.229,147.09 119.329,147.09 119.653,147.413 119.753,147.413 119.936,147.23 119.936,147.13 119.612,146.807 119.612,146.707 119.795,146.524 119.895,146.524 120.183,146.812 120.283,146.812 120.466,146.629 120.466,146.529 120.178,146.241 120.178,146.141 120.269,146.05 120.269,145.502 121.499,144.272 121.833,144.272 123.318,145.758 U5.4@123.318,146.504
SD_DQ2: U1.K16 U5.5 | length 46.9
  Top Layer w0.1: U1.K16@114.077,152.089 120.185,152.089 120.256,152.16 120.256,152.533 120.326,152.604 120.585,152.604 120.656,152.533 120.656,152.16 120.726,152.089 120.985,152.089 121.056,152.16 121.056,152.533 121.126,152.604 121.385,152.604 121.456,152.533 121.456,152.16 121.526,152.089 121.785,152.089 121.856,152.16 121.856,152.533 121.926,152.604 122.185,152.604 122.256,152.533 122.256,152.16 122.326,152.089 122.866,152.089 123.358,151.597 123.458,151.597 124.477,152.617 124.577,152.617 124.76,152.434 124.76,152.334 123.74,151.315 123.74,151.215 123.923,151.032 124.023,151.032 125.075,152.083 125.175,152.083 125.357,151.9 125.357,151.8 124.306,150.749 124.306,150.649 124.46,150.495 124.46,149.807 124.531,149.737 127.547,149.737 127.617,149.666 127.617,149.407 127.547,149.337 124.531,149.337 124.46,149.266 124.46,149.007 124.531,148.937 128.292,148.937 128.362,148.866 128.362,148.607 128.292,148.537 124.531,148.537 124.46,148.466 124.46,148.207 124.531,148.137 129.092,148.137 129.162,148.066 129.162,147.807 129.092,147.737 124.531,147.737 124.46,147.666 124.46,146.846 U5.5@124.118,146.504
SD_DQ3: U1.M15 U5.7 | length 46.9
  Top Layer w0.1: U1.M15@113.277,150.489 113.404,150.616 113.41,150.616 113.919,150.107 114.235,150.107 114.362,150.234 114.961,150.234 115.032,150.163 115.032,149.325 115.102,149.254 115.361,149.254 115.432,149.325 115.432,150.163 115.561,150.292 116.035,150.292 116.24,150.498 116.54,150.498 116.839,150.199 116.839,150.021 116.686,149.867 116.586,149.867 116.35,150.103 116.25,150.103 116.067,149.92 116.067,149.82 116.303,149.584 116.303,149.484 116.12,149.301 116.02,149.301 115.926,149.395 115.826,149.395 115.643,149.212 115.643,149.112 115.737,149.019 115.737,148.919 115.682,148.864 115.682,148.715 115.787,148.611 115.887,148.611 116.606,149.33 116.706,149.33 116.889,149.147 116.889,149.047 116.17,148.328 116.17,148.228 116.352,148.045 116.452,148.045 117.172,148.764 117.272,148.764 117.455,148.582 117.455,148.482 116.735,147.762 116.735,147.662 116.918,147.479 117.018,147.479 117.737,148.199 117.837,148.199 118.02,148.016 118.02,147.916 117.301,147.197 117.301,147.097 117.484,146.914 117.584,146.914 118.303,147.633 118.403,147.633 118.586,147.45 118.586,147.35 117.867,146.631 117.867,146.531 118.049,146.348 118.149,146.348 118.869,147.067 118.969,147.067 119.152,146.885 119.152,146.785 118.432,146.065 118.432,145.965 118.615,145.782 118.715,145.782 119.434,146.502 119.534,146.502 119.736,146.301 119.736,145.653 119.29,145.207 119.29,145.107 119.473,144.925 119.573,144.925 120.018,145.37 120.118,145.37 120.301,145.187 120.301,145.087 119.856,144.642 119.856,144.542 120.039,144.359 120.139,144.359 120.584,144.804 120.684,144.804 120.867,144.622 120.867,144.522 120.428,144.083 120.428,143.983 120.611,143.8 120.711,143.8 121.15,144.239 121.25,144.239 121.417,144.072 121.634,144.072 121.705,144.001 121.705,143.575 121.775,143.504 122.034,143.504 122.105,143.575 122.105,144.103 122.255,144.253 122.355,144.253 122.671,143.937 122.771,143.937 122.954,144.119 122.954,144.219 122.638,144.536 122.638,144.636 122.705,144.703 122.847,144.703 122.953,144.597 123.043,144.686 123.043,145.199 123.113,145.27 123.372,145.27 123.443,145.199 123.443,144.143 123.513,144.072 123.772,144.072 123.843,144.143 123.843,144.937 123.913,145.007 124.172,145.007 124.243,144.937 124.243,144.143 124.313,144.072 124.739,144.072 124.924,144.257 124.924,144.357 124.582,144.7 124.582,144.841 124.723,144.983 124.865,144.983 125.207,144.64 125.307,144.64 125.464,144.797 125.464,144.897 125.103,145.258 125.103,145.399 125.244,145.541 125.386,145.541 125.747,145.18 125.847,145.18 125.953,145.286 125.953,146.269 U5.7@125.718,146.504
